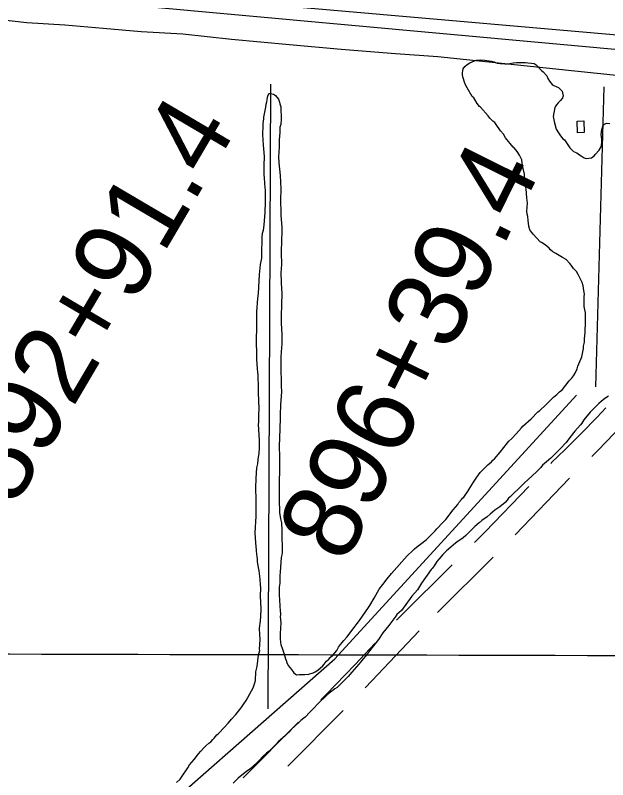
# Model space of a CAD drawing. Extents: x 3161514 to 3199414, y 831166 to 856601.
# Drawn here: x 3188637 to 3189391, y 848532 to 849505 of the extents above; entities that cross this region are included whole.
import ezdxf

# ---------------------------------------------------------------- set-up
doc = ezdxf.new("R2010")
doc.units = 0
for name, color, linetype in [('V-BLDG-OTLN', 7, 'Continuous'), ('V-GRID-MAJR', 7, 'Continuous'), ('V-ROAD-CNTR', 7, 'Continuous'), ('V-SITE-VEGE', 7, 'Continuous'), ('V-SURV-IDEN', 7, 'Continuous'), ('V-TOPO-SHOR', 7, 'Continuous')]:
    doc.layers.add(name, color=color, linetype=linetype)

msp = doc.modelspace()

# ---------------------------------------------------------------- linework, layer by layer
at = {"layer": 'V-BLDG-OTLN'}
msp.add_lwpolyline([(3189351.839, 849370.47), (3189360.2830000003, 849370.697), (3189360.69, 849355.775), (3189352.242, 849355.5480000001)], close=True, dxfattribs=at)
at = {"layer": 'V-GRID-MAJR'}
msp.add_spline([(3165741.648, 848757.608), (3170973.071, 848741.248), (3176204.497, 848725.65), (3181435.9250000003, 848710.812), (3186667.355, 848696.736), (3191898.788, 848683.42), (3197130.222, 848670.865), (3197130.223, 848670.865)], degree=3, dxfattribs=at)
at = {"layer": 'V-ROAD-CNTR'}
for p, q in [((3189342.2073591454, 848915.8975631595), (3189272.8240144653, 848843.8841221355)), ((3189244.968202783, 848815.2577957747), (3189174.091124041, 848744.7139169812)), ((3188997.091134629, 848605.3666039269), (3188926.482968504, 848534.5544065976))]:
    msp.add_line(p, q, dxfattribs=at)
for points in [[(3191674.7236136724, 849538.7428950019), (3191611.4387402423, 849581.3688097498), (3191543.718875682, 849618.615735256), (3191492.363978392, 849639.495693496), (3191451.732059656, 849654.16866415), (3191393.789175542, 849669.211634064), (3191330.4003023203, 849677.870616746), (3191264.9754331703, 849681.5706093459), (3191214.712533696, 849681.8206088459), (3191154.8636533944, 849670.340631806), (3191102.108758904, 849656.257659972), (3190975.925011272, 849620.380731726), (3190341.461280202, 849423.1531261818), (3190309.274344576, 849414.1431442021), (3190285.1443928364, 849410.360151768), (3190235.20249272, 849402.59916729), (3190194.85757341, 849396.7411790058), (3190165.4416322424, 849395.200182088), (3190132.005699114, 849394.527183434), (3189441.717079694, 849457.750056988), (3188534.061895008, 849540.7958908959), (3187119.630723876, 849717.1825381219), (3185344.2432746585, 849941.7760889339)], [(3189439.053055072, 849016.1926120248), (3189438.7755925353, 849015.8757142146), (3189419.0131750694, 848994.0812597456), (3189398.873918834, 848972.6343644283), (3189378.3620391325, 848951.5423120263), (3189370.3316808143, 848943.5686175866)], [(3189388.371947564, 849005.2759285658), (3189377.184081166, 848993.3616355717), (3189357.0379608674, 848972.6456879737), (3189336.5148907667, 848952.2674329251), (3189318.892, 848935.2544981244), (3189318.892, 848934.9364030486), (3189318.1811470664, 848934.1986039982)], [(3189290.4278190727, 848905.3932378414), (3189234.549737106, 848847.397), (3189234.732488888, 848847.397), (3189221.0660246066, 848833.7947830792)], [(3189192.7151929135, 848805.577231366), (3189127.551485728, 848740.71986502), (3189121.891778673, 848734.9799372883)], [(3189150.5696521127, 848721.5107043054), (3189090.470557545, 848657.6696387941), (3189081.903571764, 848648.8150290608)], [(3189094.594597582, 848705.8176015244), (3189068.7674424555, 848678.3823612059), (3189031.864324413, 848640.2402752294), (3189025.3344010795, 848633.6914828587)], [(3189054.090061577, 848620.0677211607), (3189053.2676755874, 848619.2177247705), (3188983.494597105, 848549.2430281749)]]:
    msp.add_lwpolyline(points, dxfattribs=at)
at = {"layer": 'V-SITE-VEGE'}
for points in [[(3189325.798, 849022.371), (3189329.507, 849025.89), (3189332.989, 849028.939), (3189341.7830000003, 849039.9450000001), (3189344.8000000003, 849042.759), (3189347.343, 849046.269), (3189349.193, 849049.544), (3189351.722, 849055.153), (3189352.869, 849058.658), (3189357.929, 849070.339), (3189359.736, 849081.073), (3189359.719, 849083.87), (3189361.0870000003, 849089.007), (3189361.296, 849093.437), (3189361.952, 849101.3640000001), (3189362.572, 849115.123), (3189362.531, 849122.348), (3189362.275, 849126.5430000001), (3189360.833, 849134.2270000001), (3189360.7600000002, 849147.047), (3189361.21, 849150.314), (3189360.733, 849152.409), (3189360.002, 849157.7660000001), (3189359.519, 849160.56), (3189358.329, 849164.984), (3189357.624, 849165.911), (3189353.143, 849175.209), (3189351.024, 849178.9280000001), (3189347.038, 849182.8690000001), (3189345.392, 849185.425), (3189342.34, 849189.3690000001), (3189337.884, 849194.2390000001), (3189333.2060000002, 849197.01), (3189326.892, 849200.469), (3189324.787, 849201.858), (3189320.811, 849204.166), (3189317.7660000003, 849206.714), (3189316.122, 849208.805), (3189310.973, 849212.735), (3189306.293, 849215.7390000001), (3189304.8880000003, 849216.8960000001), (3189295.975, 849226.637), (3189294.097, 849228.721), (3189291.748, 849231.976), (3189290.323, 849236.862), (3189289.348, 849244.081), (3189288.8540000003, 849249.208), (3189288.14, 849252.001), (3189287.65, 849255.962), (3189288.5270000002, 849265.991), (3189287.556, 849272.743), (3189286.792, 849284.1630000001), (3189285.1210000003, 849291.147), (3189284.6380000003, 849294.1730000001), (3189284.588, 849303.0310000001), (3189282.915, 849310.015), (3189282.194, 849313.974), (3189281.455, 849320.963), (3189278.389, 849327.238), (3189275.3340000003, 849331.883), (3189271.811, 849336.2930000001), (3189270.406, 849337.452), (3189260.7830000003, 849349.285), (3189257.958, 849353.93), (3189254.2060000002, 849357.872), (3189248.566, 849366.232), (3189246.9220000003, 849368.555), (3189244.579, 849370.1730000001), (3189240.829, 849374.115), (3189238.482, 849377.132), (3189228.629, 849388.0310000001), (3189227.457, 849389.1900000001), (3189224.637, 849392.905), (3189221.582, 849397.784), (3189220.171, 849399.873), (3189218.293, 849401.96), (3189211.94, 849412.6460000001), (3189209.818, 849416.599), (3189208.874, 849418.9230000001), (3189206.498, 849426.837), (3189206.017, 849429.63), (3189206.005, 849431.496), (3189206.451, 849434.996), (3189206.906, 849437.095), (3189208.755, 849439.903), (3189212.003, 849442.486), (3189215.256, 849444.601), (3189221.303, 849446.9670000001), (3189223.861, 849447.915), (3189228.52, 849448.64), (3189234.349, 849448.206), (3189236.684, 849447.753), (3189242.75, 849446.856), (3189246.252, 849445.709), (3189247.8880000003, 849445.019), (3189249.99, 849444.331), (3189253.955, 849443.888), (3189259.552, 849443.452), (3189262.585, 849443.237), (3189266.31, 849443.725), (3189270.269, 849444.443)], [(3189270.269, 849444.443), (3189270.969, 849444.4500000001), (3189274.697, 849444.937), (3189277.7260000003, 849445.187), (3189280.757, 849444.9720000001), (3189283.786, 849444.988), (3189285.883, 849445.234), (3189288.916, 849444.783), (3189293.813, 849444.345), (3189297.0810000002, 849443.665), (3189299.654, 849442.047), (3189301.5300000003, 849440.194), (3189305.048, 849436.2490000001), (3189306.9220000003, 849434.6290000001), (3189308.562, 849433.007), (3189313.021, 849427.904), (3189314.436, 849424.881), (3189316.556, 849421.164), (3189320.074, 849417.2170000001), (3189321.477, 849416.296), (3189322.182, 849415.599), (3189325.919, 849414.223), (3189328.025, 849413.068), (3189332.7120000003, 849408.433), (3189333.19, 849406.338), (3189333.91, 849402.613), (3189332.9930000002, 849400.041), (3189331.144, 849397.237), (3189327.666, 849393.719)], [(3188945.7, 849046.802), (3188945.444, 849050.763), (3188944.952, 849055.188), (3188943.951, 849067.5380000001), (3188943.787, 849096.675), (3188943.984, 849102.968), (3188943.898, 849118.355), (3188944.08, 849127.446), (3188945.38, 849144.471), (3188946.2770000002, 849150.768), (3188947.307, 849175.019), (3188948.866, 849188.081), (3188950.22, 849195.7810000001), (3188950.4250000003, 849200.91), (3188950.771, 849222.125), (3188951.436, 849227.9550000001), (3188952.348, 849231.691), (3188953.48, 849237.757), (3188954.346, 849249.185), (3188954.787, 849253.85), (3188954.7600000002, 849258.745), (3188954.969, 849262.708), (3188955.168, 849269.0040000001), (3188955.094, 849282.057), (3188954.346, 849290.6780000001), (3188953.832, 849299.066), (3188953.589, 849301.1630000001), (3188953.5130000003, 849314.451), (3188953.687, 849324.941), (3188953.1890000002, 849330.534), (3188952.438, 849339.8520000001), (3188951.893, 849353.6020000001), (3188952.065, 849364.559), (3188952.278, 849367.59), (3188953.181, 849373.191), (3188953.169, 849375.522), (3188955.428, 849388.121), (3188955.872, 849391.855), (3188956.79, 849394.89), (3188957.24, 849397.456), (3188957.687, 849400.956), (3188959.294, 849405.394), (3188959.524, 849405.628), (3188961.392, 849405.4060000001), (3188965.125, 849404.729), (3188967.699, 849402.877), (3188971.6890000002, 849398.238), (3188973.108, 849394.515), (3188973.3540000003, 849392.4180000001), (3188974.542, 849388.463), (3188974.796, 849384.736), (3188975.076, 849376.345), (3188975.095, 849373.081), (3188974.433, 849366.318), (3188973.52, 849362.816), (3188973.327, 849355.822), (3188972.678, 849346.7270000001), (3188972.701, 849342.764), (3188972.494, 849338.101), (3188972.0700000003, 849330.638), (3188971.634, 849325.508), (3188971.912, 849317.351), (3188973.6350000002, 849301.278), (3188974.382, 849292.6560000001), (3188974.665, 849284.034), (3188974.044, 849269.81), (3188974.603, 849253.4940000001), (3188974.62, 849250.465), (3188975.8710000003, 849235.3200000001), (3188975.9080000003, 849228.7930000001), (3188975.2630000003, 849219.233), (3188974.886, 849203.3790000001), (3188975.441, 849187.763), (3188975.236, 849182.635), (3188974.568, 849177.036), (3188975.6210000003, 849155.598), (3188975.873, 849152.569), (3188975.502, 849135.316), (3188974.867, 849124.1240000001), (3188975.162, 849113.169), (3188975.943, 849098.721), (3188975.736, 849094.057), (3188976.008, 849087.0650000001), (3188975.134, 849076.805), (3188974.7060000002, 849070.042), (3188974.552, 849055.821), (3188974.89, 849037.408), (3188975.146, 849033.447), (3188975.418, 849025.99), (3188974.349, 849009.432), (3188973.723, 848996.607), (3188973.145, 848974.925), (3188972.934, 848970.962), (3188972.572, 848952.778), (3188972.838, 848946.718), (3188972.883, 848938.792), (3188972.721, 848926.203), (3188972.572, 848911.286), (3188972.373, 848905.223), (3188972.643, 848898.696), (3188972.699, 848888.674)], [(3189327.666, 849393.719), (3189325.35, 849391.142), (3189323.734, 849388.5700000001), (3189323.271, 849387.634), (3189321.471, 849376.435), (3189322.44, 849369.9130000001), (3189325.057, 849360.371), (3189327.881, 849355.724), (3189330.703, 849351.544), (3189333.519, 849348.067), (3189335.627, 849346.4450000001), (3189342.4420000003, 849336.459), (3189347.366, 849331.59), (3189351.339, 849329.983), (3189352.975, 849328.826), (3189354.845, 849327.671), (3189356.719, 849326.282), (3189360.93, 849323.742), (3189363.264, 849322.823), (3189370.021, 849323.794), (3189373.732, 849326.612), (3189374.893, 849327.783), (3189379.988, 849333.64), (3189382.757, 849338.554), (3189382.751, 849339.7170000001), (3189383.1920000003, 849344.149), (3189383.173, 849347.411), (3189382.4420000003, 849353.236), (3189383.103, 849359.767), (3189384.48, 849363.969), (3189385.6350000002, 849365.608), (3189386.563, 849366.546), (3189389.352, 849367.961), (3189393.552, 849367.285)], [(3188841.862, 848528.2540000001), (3188846.265, 848532.709), (3188848.35, 848535.049), (3188856.21, 848546.983), (3188858.518, 848550.958), (3188864.077, 848557.5160000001), (3188869.86, 848565.01), (3188872.873, 848568.291), (3188876.809, 848572.974), (3188879.128, 848575.317), (3188882.841, 848578.371), (3188885.39, 848580.2490000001), (3188887.9420000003, 848583.061), (3188889.798, 848584.703), (3188891.418, 848586.811), (3188893.271, 848588.9180000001), (3188895.358, 848590.794), (3188903.005, 848598.765), (3188907.404, 848603.9180000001), (3188910.185, 848606.965), (3188911.805, 848609.0700000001), (3188917.366, 848614.93), (3188924.079, 848623.359), (3188926.8540000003, 848627.103), (3188930.553, 848632.719), (3188937.475, 848645.113), (3188939.318, 848649.086), (3188941.157, 848653.9890000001), (3188942.296, 848658.427), (3188942.935, 848669.386), (3188944.295, 848675.921), (3188944.737, 848680.351), (3188945.19, 848682.688), (3188945.855, 848688.518), (3188946.085, 848689.219), (3188946.306, 848691.552), (3188947.228, 848693.421), (3188947.676, 848696.456), (3188947.664, 848698.552), (3188947.8710000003, 848703.215), (3188948.293, 848711.143), (3188947.7970000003, 848716.502), (3188947.5160000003, 848724.893), (3188948.626, 848734.4550000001), (3188949.063, 848739.819), (3188949.474, 848749.612), (3188948.917, 848765.462), (3188949.091, 848776.183), (3188948.835, 848780.1460000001), (3188948.098, 848786.669), (3188947.84, 848791.328), (3188947.103, 848798.082), (3188945.419, 848806.7000000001), (3188944.938, 848809.961), (3188944.9220000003, 848812.758), (3188944.666, 848816.719), (3188944.1920000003, 848818.116), (3188943.693, 848824.174), (3188942.708, 848833.726), (3188941.936, 848846.309), (3188943.216, 848867.528), (3188943.416, 848873.123), (3188943.328, 848888.741), (3188942.779, 848903.192), (3188943.1750000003, 848915.7810000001), (3188944.2660000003, 848928.841), (3188945.169, 848933.9770000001), (3188945.839, 848939.572), (3188947.191, 848947.74), (3188947.619, 848954.502), (3188947.566, 848963.8250000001), (3188946.2830000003, 848984.5650000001), (3188946.503, 848986.898), (3188946.701, 848992.96), (3188946.681, 848996.687), (3188946.8710000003, 849004.381), (3188946.585, 849014.171), (3188946.562, 849017.9), (3188946.306, 849021.63), (3188946.23, 849035.149), (3188945.72, 849042.839), (3188945.7, 849046.802)], [(3188972.699, 848888.674), (3188973.026, 848872.126), (3188974.237, 848864.206), (3188975.433, 848858.853), (3188975.953, 848849.299), (3188976.117, 848820.16), (3188975.214, 848814.794), (3188974.1180000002, 848802.666), (3188973.688, 848796.137), (3188973.4790000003, 848791.942), (3188973.299, 848782.38), (3188972.629, 848777.248), (3188972.684, 848767.225), (3188973.2290000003, 848753.708), (3188973.237, 848751.845), (3188973.725, 848748.117), (3188973.995, 848741.826), (3188973.774, 848739.7270000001), (3188974.517, 848731.571), (3188973.895, 848718.282), (3188973.931, 848711.755), (3188974.1920000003, 848706.86), (3188974.673, 848704.296), (3188976.805, 848698.017), (3188978.937, 848691.736), (3188980.372, 848685.682), (3188981.786, 848682.893), (3188982.023, 848681.961), (3188984.149, 848677.312), (3188986.029, 848674.758), (3188988.374, 848672.206), (3188990.961, 848668.0260000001), (3188994.471, 848665.716), (3188997.967, 848665.968), (3188999.833, 848665.745), (3189004.9590000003, 848666.007), (3189010.0870000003, 848666.269), (3189015.903, 848668.167), (3189018.228, 848669.345), (3189021.711, 848671.463), (3189028.208, 848676.861), (3189032.836, 848682.714), (3189035.619, 848685.295), (3189037.473, 848687.402), (3189040.719, 848690.685), (3189045.8140000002, 848696.309), (3189048.12, 848700.751), (3189050.432, 848704.259), (3189054.8340000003, 848709.412), (3189058.536, 848713.631), (3189067.793, 848725.804), (3189071.9590000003, 848730.9550000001), (3189074.736, 848734.701), (3189078.666, 848740.318), (3189086.0640000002, 848751.314), (3189087.915, 848753.889), (3189093.225, 848763.01), (3189099.918, 848774.706), (3189104.315, 848780.322), (3189109.867, 848787.814), (3189115.426, 848794.607), (3189135.578, 848816.865), (3189142.5330000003, 848823.664), (3189144.62, 848825.773), (3189149.261, 848829.529), (3189152.2800000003, 848831.645), (3189159.474, 848837.279), (3189165.501, 848843.14), (3189171.0640000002, 848848.7660000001), (3189173.378, 848851.576), (3189181.0270000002, 848859.313), (3189184.736, 848863.297), (3189193.989, 848875.704), (3189200.012, 848882.263), (3189201.399, 848884.836), (3189204.4050000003, 848888.817), (3189206.029, 848890.224), (3189207.42, 848891.8640000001), (3189212.972, 848899.587), (3189217.586, 848907.54), (3189219.667, 848910.814), (3189220.593, 848911.986), (3189224.06, 848917.133), (3189228.455, 848923.2170000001), (3189237.958, 848932.828), (3189242.596, 848936.818), (3189244.452, 848938.694), (3189246.541, 848940.336), (3189253.719, 848948.77), (3189262.9760000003, 848960.71), (3189265.061, 848963.0530000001), (3189268.538, 848966.336), (3189274.332, 848972.1950000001), (3189280.8140000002, 848980.16), (3189282.667, 848982.267), (3189293.106, 848991.4180000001), (3189301.915, 849000.324), (3189303.77, 849001.733), (3189312.585, 849009.708), (3189321.856, 849019.086), (3189325.798, 849022.371)], [(3189391.779, 849020.4130000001), (3189387.136, 849017.122), (3189382.264, 849013.366), (3189379.245, 849010.786), (3189368.583, 849000.003), (3189360.481, 848990.166), (3189357.94, 848985.956), (3189356.088, 848983.615), (3189348.6750000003, 848975.6460000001), (3189342.662, 848967.454), (3189338.031, 848961.367), (3189330.15, 848953.3960000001), (3189326.9080000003, 848949.649), (3189320.187, 848942.851), (3189318.329, 848941.442), (3189312.7630000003, 848936.748), (3189307.893, 848932.292), (3189305.578, 848929.2490000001), (3189300.248, 848923.856), (3189289.346, 848914.2390000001), (3189284.478, 848909.549), (3189279.378, 848904.392), (3189268.9420000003, 848894.775), (3189266.625, 848892.196), (3189264.539, 848890.3200000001), (3189262.919, 848887.981), (3189260.139, 848884.936), (3189253.41, 848879.535), (3189246.907, 848875.071), (3189244.126, 848872.49), (3189240.876, 848869.908), (3189237.165, 848866.623), (3189230.665, 848861.925), (3189228.809, 848860.282), (3189227.879, 848859.809), (3189226.952, 848859.107), (3189221.617, 848854.181), (3189210.0270000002, 848842.694), (3189206.5470000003, 848839.876), (3189198.6520000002, 848834.238), (3189196.795, 848833.06), (3189193.776, 848830.713), (3189185.428, 848823.2050000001), (3189180.792, 848818.517), (3189176.159, 848813.3640000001), (3189173.382, 848809.85), (3189169.917, 848804.47), (3189167.3710000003, 848800.96), (3189165.9790000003, 848799.786), (3189153.723, 848782.235), (3189152.339, 848779.892), (3189148.411, 848773.811), (3189141.4620000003, 848765.8470000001), (3189128.043, 848747.589), (3189122.4790000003, 848742.43), (3189120.859, 848740.323), (3189112.303, 848728.153), (3189104.664, 848719.019), (3189099.1180000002, 848710.362), (3189086.1520000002, 848694.437), (3189085.23, 848692.567), (3189079.44, 848686.008), (3189075.967, 848681.7930000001), (3189073.884, 848678.985), (3189068.094, 848672.4230000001), (3189064.85, 848668.909)], [(3189064.85, 848668.909), (3189060.451, 848663.523), (3189048.169, 848650.866), (3189046.3140000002, 848649.223), (3189043.293, 848647.5750000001), (3189034.008, 848640.53), (3189020.792, 848627.867), (3189016.853, 848623.417), (3189011.525, 848617.791), (3189005.497, 848611.698), (3189003.873, 848610.522), (3188999.929, 848607.235), (3188997.842, 848605.359), (3188987.87, 848595.98), (3188984.86, 848592.699), (3188980.454, 848588.478), (3188971.177, 848580.267), (3188968.629, 848577.2220000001), (3188959.821, 848568.313), (3188956.571, 848565.964), (3188952.628, 848562.212), (3188946.14, 848555.648), (3188937.561, 848547.444), (3188934.544, 848545.095), (3188931.526, 848542.979), (3188928.974, 848540.634), (3188924.794, 848537.812), (3188920.389, 848533.8250000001), (3188913.896, 848527.4940000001)]]:
    msp.add_lwpolyline(points, dxfattribs=at)
at = {"layer": 'V-TOPO-SHOR'}
for p, q in [((3189174.3000000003, 849452.752), (3189732.274570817, 849393.9780511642)), ((3188958.5236937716, 848622.0492500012), (3188962.0597837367, 849417.6694922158)), ((3189375.7823096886, 849032.2356859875), (3189386.3905795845, 849414.1334022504))]:
    msp.add_line(p, q, dxfattribs=at)
for points in [[(3191187.0502780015, 849752.5626124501), (3191177.7605225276, 849722.8353949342), (3191172.1866692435, 849713.5456394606), (3191164.7548648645, 849707.9717861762), (3191149.8912561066, 849698.6820307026), (3191140.6015006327, 849691.2502263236), (3191088.57886998, 849680.1025197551), (3190852.6190809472, 849611.3583292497), (3190638.954705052, 849537.0402854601), (3190389.9892583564, 849455.2904372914), (3190324.9609700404, 849444.1427307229), (3190245.0690729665, 849429.2791219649), (3190167.035126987, 849427.4211708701), (3190085.285278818, 849427.4211708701), (3190036.978550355, 849432.9950241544), (3189752.712032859, 849444.1427307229), (3189514.8942927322, 849470.1540460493), (3188959.366915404, 849518.4607745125), (3188903.6283825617, 849524.0346277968), (3188866.469360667, 849542.6141387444)], [(3188602.553, 849501.318), (3188651.455, 849496.014), (3188699.473, 849492.885), (3188748.629, 849488.6290000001), (3188796.915, 849484.541), (3188849.898, 849481.35), (3188911.787, 849474.639), (3188985.611, 849467.905), (3189051.416, 849462.087), (3189120.701, 849456.721), (3189174.3000000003, 849452.752)], [(3187811.7060000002, 847458.936), (3187989.6350432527, 847610.7275198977), (3188530.656807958, 848197.7184541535), (3188753.430475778, 848431.1003918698), (3189043.389852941, 848685.6988693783), (3189351.029679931, 849021.6274160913)]]:
    msp.add_lwpolyline(points, dxfattribs=at)

# ---------------------------------------------------------------- texts
at = {"layer": 'V-SURV-IDEN'}
for s, height, rotation, p in [('892+91.4', 100.00000000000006, 59.51506928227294, (3188634.0695887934, 848876.2215712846)), ('896+39.4', 100.00000000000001, 63.61998181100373, (3189056.3962276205, 848804.5222616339))]:
    msp.add_text(s, height=height, rotation=rotation, dxfattribs=at).set_placement(p)

doc.saveas('drawing.dxf')
